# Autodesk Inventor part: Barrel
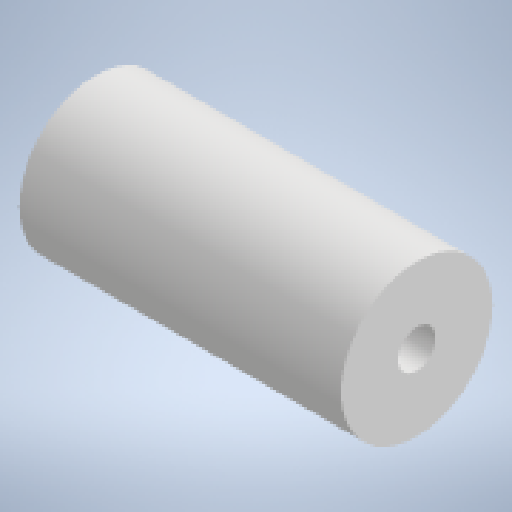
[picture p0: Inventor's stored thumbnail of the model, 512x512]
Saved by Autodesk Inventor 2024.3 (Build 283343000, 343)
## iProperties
Created: 2024-12
Part Number: Barrel
Material: Generic
Document SubType Name: Modeling
Designer: ruhr
Density: 1 g/cm^3
Appearance: Default
Author: ruhr
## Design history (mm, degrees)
sketch "Sketch1"
  geometry: C1 r 20 at (0, 0); C2 r 5 at (0, 0); 1 further point
  constraints: 2 centre point, 2 coincident
  dimensions: "d0" = 40 diameter of C1; "d1" = 10 diameter of C2
extrude "Extrusion1" new body sketch "Sketch1" distance "d2" = 85; taper "d3" = 0 deg
body "Solid1"
